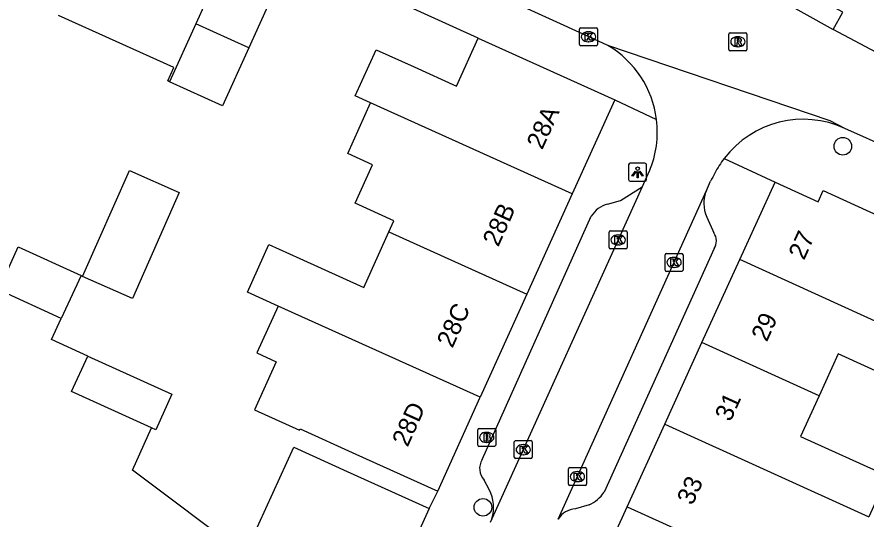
# Model space of a CAD drawing. Extents: x 161845 to 162341, y 381620 to 382158.
# Drawn here: x 162036.15 to 162083.32, y 381718.91 to 381746.81 of the extents above; entities that cross this region are included whole.
import ezdxf

# ---------------------------------------------------------------- set-up
doc = ezdxf.new("R2010")
doc.units = 0
for name, color, linetype in [('IMGEO_Boom', 7, 'Continuous'), ('IMGEO_Brandkraan', 7, 'Continuous'), ('IMGEO_Kolk', 7, 'Continuous'), ('IMGEO_Lichtpunt', 7, 'Continuous'), ('IMGEO_Muur', 7, 'Continuous'), ('IMGEO_Pand', 7, 'Continuous'), ('IMGEO_Pand_nummerreeks', 7, 'Continuous'), ('IMGEO_Rijbaan_lokaal_open', 7, 'Continuous'), ('IMGEO_Rioolput', 7, 'Continuous'), ('IMGEO_Voetpad_open', 7, 'Continuous')]:
    doc.layers.add(name, color=color, linetype=linetype)

msp = doc.modelspace()

# ---------------------------------------------------------------- linework, layer by layer
at = {"layer": 'IMGEO_Boom'}
for centre in [(162082.036, 381739.628), (162062.04, 381719.56)]:
    msp.add_circle(centre, 0.489, dxfattribs=at)
at = {"layer": 'IMGEO_Brandkraan'}
for p, q in [((162061.823, 381723.949), (162062.675, 381723.949)), ((162061.748, 381723.023), (162061.748, 381723.875)), ((162062.236, 381723.729), (162062.261, 381723.729)), ((162062.749, 381723.875), (162062.749, 381723.023)), ((162062.675, 381722.949), (162061.823, 381722.949)), ((162062.259, 381723.169), (162062.234, 381723.169))]:
    msp.add_line(p, q, dxfattribs=at)
for points in [[(162061.823, 381723.949), (162062.675, 381723.949)], [(162061.748, 381723.023), (162061.748, 381723.875)], [(162062.096, 381723.649), (162062.096, 381723.249), (162062.309, 381723.249)], [(162062.327, 381723.649), (162062.096, 381723.649)], [(162062.275, 381723.568), (162062.221, 381723.568), (162062.221, 381723.492)], [(162062.221, 381723.492), (162062.274, 381723.492)], [(162062.283, 381723.416), (162062.221, 381723.416), (162062.221, 381723.335)], [(162062.749, 381723.875), (162062.749, 381723.023)], [(162062.675, 381722.949), (162061.823, 381722.949)], [(162062.221, 381723.335), (162062.283, 381723.335)]]:
    msp.add_lwpolyline(points, dxfattribs=at)
for centre, radius, start, end in [((162061.825, 381723.873), 0.0765, 91.552, 178.448), ((162061.825, 381723.873), 0.0765, 91.552, 178.448), ((162062.673, 381723.873), 0.0765, 1.552, 88.448), ((162062.673, 381723.873), 0.0765, 1.552, 88.448), ((162062.276, 381723.53), 0.0379, 267.8285, 90.9355), ((162062.284, 381723.375), 0.0404, 269.8759, 90.5077), ((162062.331, 381723.504), 0.145, 59.4692, 91.5367), ((162062.356, 381723.551), 0.0922, 285.5137, 58.1501), ((162062.361, 381723.359), 0.105, 301.3115, 78.989), ((162061.825, 381723.025), 0.0765, 181.552, 268.448), ((162061.825, 381723.025), 0.0765, 181.552, 268.448), ((162062.315, 381723.5), 0.251, 268.6676, 293.5347), ((162062.673, 381723.025), 0.0765, 271.552, 358.448), ((162062.673, 381723.025), 0.0765, 271.552, 358.448)]:
    msp.add_arc(centre, radius, start, end, dxfattribs=at)
for centre, major_axis, ratio, start_param, end_param in [((162062.235, 381723.449), (-0.387, 0.002), 0.722429, 4.712389, 7.853982), ((162062.26, 381723.449), (-0.39, 0.002), 0.717154, 1.570796, 4.712389)]:
    msp.add_ellipse(centre, major_axis=major_axis, ratio=ratio, start_param=start_param, end_param=end_param, dxfattribs=at)
at = {"layer": 'IMGEO_Kolk'}
for p, q in [((162067.403, 381745.29), (162067.403, 381746.142)), ((162067.478, 381746.216), (162068.33, 381746.216)), ((162068.404, 381746.142), (162068.404, 381745.29)), ((162067.891, 381745.996), (162067.916, 381745.996)), ((162068.33, 381745.216), (162067.478, 381745.216)), ((162067.914, 381745.436), (162067.889, 381745.436)), ((162069.053, 381733.997), (162069.053, 381734.849)), ((162069.128, 381734.923), (162069.98, 381734.923)), ((162070.054, 381734.849), (162070.054, 381733.997)), ((162069.541, 381734.703), (162069.566, 381734.703)), ((162069.98, 381733.923), (162069.128, 381733.923)), ((162069.564, 381734.143), (162069.539, 381734.143)), ((162072.156, 381732.749), (162072.156, 381733.601)), ((162072.231, 381733.675), (162073.083, 381733.675)), ((162072.644, 381733.455), (162072.669, 381733.455)), ((162073.157, 381733.601), (162073.157, 381732.749)), ((162072.667, 381732.895), (162072.642, 381732.895)), ((162073.083, 381732.675), (162072.231, 381732.675)), ((162063.781, 381722.34), (162063.781, 381723.192)), ((162063.856, 381723.266), (162064.708, 381723.266)), ((162064.269, 381723.046), (162064.294, 381723.046)), ((162064.782, 381723.192), (162064.782, 381722.34)), ((162064.292, 381722.486), (162064.267, 381722.486)), ((162064.708, 381722.266), (162063.856, 381722.266)), ((162066.788, 381720.841), (162066.788, 381721.693)), ((162066.863, 381721.767), (162067.715, 381721.767)), ((162067.276, 381721.547), (162067.301, 381721.547)), ((162067.789, 381721.693), (162067.789, 381720.841)), ((162067.715, 381720.767), (162066.863, 381720.767)), ((162067.299, 381720.987), (162067.274, 381720.987))]:
    msp.add_line(p, q, dxfattribs=at)
for points in [[(162067.403, 381745.29), (162067.403, 381746.142)], [(162067.478, 381746.216), (162068.33, 381746.216)], [(162068.404, 381746.142), (162068.404, 381745.29)], [(162067.724, 381745.916), (162067.847, 381745.916), (162067.847, 381745.765), (162067.977, 381745.916), (162068.141, 381745.916), (162067.995, 381745.765), (162068.148, 381745.516), (162067.996, 381745.516), (162067.911, 381745.68), (162067.847, 381745.613), (162067.847, 381745.516), (162067.724, 381745.516), (162067.724, 381745.916)], [(162068.33, 381745.216), (162067.478, 381745.216)], [(162069.053, 381733.997), (162069.053, 381734.849)], [(162069.128, 381734.923), (162069.98, 381734.923)], [(162070.054, 381734.849), (162070.054, 381733.997)], [(162069.374, 381734.623), (162069.497, 381734.623), (162069.497, 381734.472), (162069.627, 381734.623), (162069.791, 381734.623), (162069.645, 381734.472), (162069.798, 381734.223), (162069.646, 381734.223), (162069.561, 381734.387), (162069.497, 381734.32), (162069.497, 381734.223), (162069.374, 381734.223), (162069.374, 381734.623)], [(162069.98, 381733.923), (162069.128, 381733.923)], [(162072.156, 381732.749), (162072.156, 381733.601)], [(162072.231, 381733.675), (162073.083, 381733.675)], [(162072.477, 381733.375), (162072.6, 381733.375), (162072.6, 381733.224), (162072.73, 381733.375), (162072.894, 381733.375), (162072.748, 381733.224), (162072.901, 381732.975), (162072.749, 381732.975), (162072.664, 381733.139), (162072.6, 381733.072), (162072.6, 381732.975), (162072.477, 381732.975), (162072.477, 381733.375)], [(162073.157, 381733.601), (162073.157, 381732.749)], [(162073.083, 381732.675), (162072.231, 381732.675)], [(162063.781, 381722.34), (162063.781, 381723.192)], [(162063.856, 381723.266), (162064.708, 381723.266)], [(162064.102, 381722.966), (162064.225, 381722.966), (162064.225, 381722.815), (162064.355, 381722.966), (162064.519, 381722.966), (162064.373, 381722.815), (162064.526, 381722.566), (162064.374, 381722.566), (162064.289, 381722.73), (162064.225, 381722.663), (162064.225, 381722.566), (162064.102, 381722.566), (162064.102, 381722.966)], [(162064.782, 381723.192), (162064.782, 381722.34)], [(162064.708, 381722.266), (162063.856, 381722.266)], [(162066.788, 381720.841), (162066.788, 381721.693)], [(162066.863, 381721.767), (162067.715, 381721.767)], [(162067.789, 381721.693), (162067.789, 381720.841)], [(162067.109, 381721.467), (162067.232, 381721.467), (162067.232, 381721.316), (162067.362, 381721.467), (162067.526, 381721.467), (162067.38, 381721.316), (162067.533, 381721.067), (162067.381, 381721.067), (162067.296, 381721.231), (162067.232, 381721.164), (162067.232, 381721.067), (162067.109, 381721.067), (162067.109, 381721.467)], [(162067.715, 381720.767), (162066.863, 381720.767)]]:
    msp.add_lwpolyline(points, dxfattribs=at)
for centre, start, end in [((162067.48, 381746.14), 91.552, 178.448), ((162067.48, 381746.14), 91.552, 178.448), ((162068.328, 381746.14), 1.552, 88.448), ((162068.328, 381746.14), 1.552, 88.448), ((162067.48, 381745.292), 181.552, 268.448), ((162067.48, 381745.292), 181.552, 268.448), ((162068.328, 381745.292), 271.552, 358.448), ((162068.328, 381745.292), 271.552, 358.448), ((162069.13, 381734.847), 91.552, 178.448), ((162069.13, 381734.847), 91.552, 178.448), ((162069.978, 381734.847), 1.552, 88.448), ((162069.978, 381734.847), 1.552, 88.448), ((162069.13, 381733.999), 181.552, 268.448), ((162069.13, 381733.999), 181.552, 268.448), ((162069.978, 381733.999), 271.552, 358.448), ((162069.978, 381733.999), 271.552, 358.448), ((162072.233, 381733.599), 91.552, 178.448), ((162072.233, 381733.599), 91.552, 178.448), ((162073.081, 381733.599), 1.552, 88.448), ((162073.081, 381733.599), 1.552, 88.448), ((162072.233, 381732.751), 181.552, 268.448), ((162072.233, 381732.751), 181.552, 268.448), ((162073.081, 381732.751), 271.552, 358.448), ((162073.081, 381732.751), 271.552, 358.448), ((162063.858, 381723.19), 91.552, 178.448), ((162063.858, 381723.19), 91.552, 178.448), ((162064.706, 381723.19), 1.552, 88.448), ((162064.706, 381723.19), 1.552, 88.448), ((162063.858, 381722.342), 181.552, 268.448), ((162063.858, 381722.342), 181.552, 268.448), ((162064.706, 381722.342), 271.552, 358.448), ((162064.706, 381722.342), 271.552, 358.448), ((162066.865, 381721.691), 91.552, 178.448), ((162066.865, 381721.691), 91.552, 178.448), ((162067.713, 381721.691), 1.552, 88.448), ((162067.713, 381721.691), 1.552, 88.448), ((162066.865, 381720.843), 181.552, 268.448), ((162066.865, 381720.843), 181.552, 268.448), ((162067.713, 381720.843), 271.552, 358.448), ((162067.713, 381720.843), 271.552, 358.448)]:
    msp.add_arc(centre, 0.0765, start, end, dxfattribs=at)
for centre, major_axis, ratio, start_param, end_param in [((162067.89, 381745.716), (-0.387, 0.002), 0.722429, 4.712389, 7.853982), ((162067.915, 381745.716), (-0.39, 0.002), 0.717154, 1.570796, 4.712389), ((162069.54, 381734.423), (-0.387, 0.002), 0.722429, 4.712389, 7.853982), ((162069.565, 381734.423), (-0.39, 0.002), 0.717154, 1.570796, 4.712389), ((162072.643, 381733.175), (-0.387, 0.002), 0.722429, 4.712389, 7.853982), ((162072.668, 381733.175), (-0.39, 0.002), 0.717154, 1.570796, 4.712389), ((162064.268, 381722.766), (-0.387, 0.002), 0.722429, 4.712389, 7.853982), ((162064.293, 381722.766), (-0.39, 0.002), 0.717154, 1.570796, 4.712389), ((162067.275, 381721.267), (-0.387, 0.002), 0.722429, 4.712389, 7.853982), ((162067.3, 381721.267), (-0.39, 0.002), 0.717154, 1.570796, 4.712389)]:
    msp.add_ellipse(centre, major_axis=major_axis, ratio=ratio, start_param=start_param, end_param=end_param, dxfattribs=at)
at = {"layer": 'IMGEO_Lichtpunt'}
for p, q in [((162070.134, 381738.588), (162070.134, 381737.781)), ((162070.134, 381738.588), (162070.134, 381737.781)), ((162071.036, 381738.683), (162070.228, 381738.683)), ((162071.036, 381738.683), (162070.228, 381738.683)), ((162071.13, 381737.781), (162071.13, 381738.588)), ((162071.13, 381737.781), (162071.13, 381738.588)), ((162070.228, 381737.687), (162071.036, 381737.687)), ((162070.228, 381737.687), (162071.036, 381737.687))]:
    msp.add_line(p, q, dxfattribs=at)
for points in [[(162070.508, 381738.252), (162070.547, 381738.224), (162070.359, 381737.962), (162070.321, 381737.989), (162070.508, 381738.252)], [(162070.61, 381738.204), (162070.657, 381738.204), (162070.657, 381737.882), (162070.61, 381737.882), (162070.61, 381738.204)], [(162070.72, 381738.224), (162070.758, 381738.251), (162070.945, 381737.989), (162070.906, 381737.961), (162070.72, 381738.224)]]:
    msp.add_lwpolyline(points, dxfattribs=at)
msp.add_circle((162070.633, 381738.386), 0.0994, dxfattribs=at)
for centre, start, end in [((162070.228, 381738.588), 90, 180), ((162070.228, 381738.588), 90, 180), ((162071.036, 381738.588), 0, 90), ((162071.036, 381738.588), 0, 90), ((162070.228, 381737.781), 180, 270), ((162070.228, 381737.781), 180, 270), ((162071.036, 381737.781), 270, 0), ((162071.036, 381737.781), 270, 360)]:
    msp.add_arc(centre, 0.0946, start, end, dxfattribs=at)
at = {"layer": 'IMGEO_Muur'}
msp.add_lwpolyline([(162061.772, 381745.637), (162051.408, 381750.366)], dxfattribs=at)
at = {"layer": 'IMGEO_Pand'}
for points in [[(162048.46, 381751.697), (162047.692, 381750), (162046.08, 381746.435)], [(162051.408, 381750.366), (162049.031, 381745.101)], [(162044.624, 381743.216), (162044.525, 381743.261), (162044.858, 381744), (162038.465, 381746.887)], [(162046.08, 381746.435), (162044.624, 381743.216)], [(162049.031, 381745.101), (162046.08, 381746.435)], [(162055.802, 381742.043), (162054.948, 381742.429), (162056.105, 381744.987), (162058.214, 381744.033), (162060.564, 381742.969), (162061.772, 381745.637)], [(162061.772, 381745.637), (162069.369, 381742.199)], [(162049.031, 381745.101), (162047.578, 381741.883), (162044.624, 381743.216)], [(162056.82, 381734.869), (162057.097, 381735.481), (162054.936, 381736.459), (162055.904, 381738.6), (162054.526, 381739.223), (162055.802, 381742.043)], [(162067.005, 381736.977), (162055.802, 381742.043)], [(162069.369, 381742.199), (162067.005, 381736.977)], [(162042.399, 381738.276), (162045.166, 381737.054), (162042.567, 381731.172), (162039.801, 381732.394), (162042.399, 381738.276)], [(162076.306, 381733.328), (162078.267, 381737.638)], [(162078.267, 381737.638), (162080.663, 381736.548), (162080.942, 381737.161), (162085.927, 381734.893)], [(162067.005, 381736.977), (162064.483, 381731.405)], [(162050.667, 381730.749), (162048.953, 381731.524), (162050.145, 381734.159), (162051.86, 381733.383), (162055.419, 381731.773), (162056.82, 381734.869)], [(162056.82, 381734.869), (162064.483, 381731.405)], [(162035.117, 381731.657), (162036.215, 381734.047), (162039.711, 381732.441), (162038.613, 381730.051)], [(162074.208, 381728.716), (162076.306, 381733.328)], [(162087.601, 381728.189), (162076.306, 381733.328)], [(162038.613, 381730.051), (162035.117, 381731.657)], [(162064.483, 381731.405), (162061.89, 381725.676)], [(162050.667, 381730.749), (162049.486, 381728.139), (162050.56, 381727.653), (162049.347, 381724.972), (162051.844, 381723.842), (162051.879, 381723.919), (162054.973, 381722.519), (162059.528, 381720.458)], [(162061.89, 381725.676), (162050.667, 381730.749)], [(162072.147, 381724.183), (162074.208, 381728.716)], [(162080.711, 381725.757), (162074.208, 381728.716)], [(162087.601, 381728.189), (162086.563, 381725.907), (162081.771, 381728.087), (162080.711, 381725.757)], [(162043.634, 381723.976), (162039.186, 381725.994), (162040.082, 381727.969)], [(162040.082, 381727.969), (162044.759, 381725.847), (162043.863, 381723.872), (162043.634, 381723.976)], [(162059.528, 381720.458), (162061.89, 381725.676)], [(162080.711, 381725.757), (162079.684, 381723.498), (162084.511, 381721.303), (162083.477, 381719.029)], [(162070.06, 381719.595), (162072.147, 381724.183)], [(162072.147, 381724.183), (162083.477, 381719.029)], [(162048.815, 381716.934), (162051.526, 381722.912), (162054.491, 381721.55), (162059.046, 381719.488)], [(162059.046, 381719.488), (162056.347, 381713.524)], [(162067.969, 381714.998), (162070.06, 381719.595)], [(162070.06, 381719.595), (162076.547, 381716.643)]]:
    msp.add_lwpolyline(points, dxfattribs=at)
at = {"layer": 'IMGEO_Rijbaan_lokaal_open'}
for points in [[(162068.985, 381745.23), (162068.214, 381745.584), (162056.86, 381750.762), (162052.77, 381752.631)], [(162073.51, 381750.574), (162081.506, 381746.115)], [(162084.495, 381744.526), (162081.506, 381746.115)], [(162082.15, 381740.62), (162081.324, 381741.038), (162068.985, 381745.23)], [(162087.294, 381738.315), (162082.15, 381740.62)], [(162071.284, 381738.243), (162070.89, 381737.372)], [(162074.46, 381737.176), (162074.689, 381737.685)], [(162070.89, 381737.372), (162062.541, 381718.913)], [(162066.227, 381718.911), (162074.46, 381737.176)], [(162040.082, 381727.969), (162038.075, 381728.88), (162038.613, 381730.051)], [(162048.815, 381716.934), (162042.565, 381721.62), (162043.634, 381723.976)], [(162062.541, 381718.913), (162062.449, 381718.709)]]:
    msp.add_lwpolyline(points, dxfattribs=at)
for centre, radius, start, end in [((162066.141, 381740.423), 5.586, 7.1726, 59.393), ((162066.148, 381740.421), 5.579, 337.0159, 7.1926), ((162079.84, 381735.589), 5.536, 65.3364, 142.6075), ((162079.878, 381735.562), 5.582, 142.6195, 152.4839), ((162079.843, 381735.285), 5.685, 149.8456, 155.0316)]:
    msp.add_arc(centre, radius, start, end, dxfattribs=at)
at = {"layer": 'IMGEO_Rioolput'}
for p, q in [((162075.705, 381745.009), (162075.705, 381745.861)), ((162075.78, 381745.935), (162076.632, 381745.935)), ((162076.193, 381745.715), (162076.218, 381745.715)), ((162076.706, 381745.861), (162076.706, 381745.009)), ((162076.216, 381745.155), (162076.191, 381745.155)), ((162076.632, 381744.935), (162075.78, 381744.935))]:
    msp.add_line(p, q, dxfattribs=at)
for points in [[(162075.705, 381745.009), (162075.705, 381745.861)], [(162075.78, 381745.935), (162076.632, 381745.935)], [(162076.294, 381745.633), (162076.042, 381745.635), (162076.042, 381745.235)], [(162076.706, 381745.861), (162076.706, 381745.009)], [(162076.042, 381745.235), (162076.166, 381745.235), (162076.166, 381745.397), (162076.177, 381745.397)], [(162076.22, 381745.554), (162076.166, 381745.554), (162076.166, 381745.473)], [(162076.166, 381745.473), (162076.218, 381745.473)], [(162076.224, 381745.368), (162076.295, 381745.235), (162076.435, 381745.235), (162076.37, 381745.361)], [(162076.632, 381744.935), (162075.78, 381744.935)]]:
    msp.add_lwpolyline(points, dxfattribs=at)
for centre, radius, start, end in [((162075.782, 381745.859), 0.0765, 91.552, 178.448), ((162075.782, 381745.859), 0.0765, 91.552, 178.448), ((162076.293, 381745.523), 0.109, 350.3612, 89.416), ((162076.63, 381745.859), 0.0765, 1.552, 88.448), ((162076.63, 381745.859), 0.0765, 1.552, 88.448), ((162076.176, 381745.344), 0.0533, 26.0293, 88.6989), ((162076.202, 381745.662), 0.19, 274.7715, 282.9687), ((162076.226, 381745.458), 0.0964, 77.0061, 93.1865), ((162076.24, 381745.515), 0.0378, 276.6634, 79.6772), ((162076.291, 381745.523), 0.112, 277.5842, 350.9817), ((162076.275, 381745.308), 0.108, 29.5134, 73.7905), ((162075.782, 381745.011), 0.0765, 181.552, 268.448), ((162075.782, 381745.011), 0.0765, 181.552, 268.448), ((162076.63, 381745.011), 0.0765, 271.552, 358.448), ((162076.63, 381745.011), 0.0765, 271.552, 358.448)]:
    msp.add_arc(centre, radius, start, end, dxfattribs=at)
for centre, major_axis, ratio, start_param, end_param in [((162076.192, 381745.435), (-0.387, 0.002), 0.722429, 4.712389, 7.853982), ((162076.217, 381745.435), (-0.39, 0.002), 0.717154, 1.570796, 4.712389)]:
    msp.add_ellipse(centre, major_axis=major_axis, ratio=ratio, start_param=start_param, end_param=end_param, dxfattribs=at)
at = {"layer": 'IMGEO_Voetpad_open'}
for points in [[(162061.772, 381745.637), (162051.408, 381750.366)], [(162081.506, 381746.115), (162082.026, 381747.073), (162079.471, 381748.488)], [(162069.369, 381742.199), (162071.683, 381741.12)], [(162075.442, 381738.951), (162078.267, 381737.638)], [(162068.968, 381736.414), (162069.691, 381736.607), (162070.89, 381737.372)], [(162061.996, 381722.217), (162068.057, 381735.737)], [(162074.48, 381735.689), (162074.865, 381734.814)], [(162074.881, 381733.938), (162068.77, 381720.405)], [(162062.384, 381720.543), (162062.115, 381721.075)], [(162059.046, 381719.488), (162059.528, 381720.458)], [(162067.935, 381719.703), (162067.174, 381719.484)]]:
    msp.add_lwpolyline(points, dxfattribs=at)
for centre, radius, start, end in [((162076.14, 381736.455), 1.828, 156.7751, 204.766), ((162069.383, 381734.905), 1.565, 105.3599, 147.8751), ((162074.236, 381734.364), 0.773, 326.5491, 35.5437), ((162062.792, 381721.723), 0.937, 148.1553, 223.7426), ((162060.5, 381719.539), 2.134, 342.9449, 28.0585), ((162067.179, 381721.45), 1.903, 293.4007, 326.7081), ((162067.275, 381718.248), 1.24, 94.672, 147.6816)]:
    msp.add_arc(centre, radius, start, end, dxfattribs=at)

# ---------------------------------------------------------------- texts
at = {"layer": 'IMGEO_Pand_nummerreeks'}
for s, rotation, p in [('28A', 65.6463, (162065.332, 381739.392)), ('28B', 65.6438, (162062.889, 381733.995)), ('27', 65.5401, (162079.878, 381733.256)), ('28C', 65.6463, (162060.343, 381728.367)), ('29', 65.5401, (162077.812, 381728.714)), ('31', 65.5401, (162075.791, 381724.275)), ('28D', 65.6438, (162057.854, 381722.871)), ('33', 65.5401, (162073.679, 381719.63))]:
    msp.add_text(s, height=1, rotation=rotation, dxfattribs=at).set_placement(p)

doc.saveas('drawing.dxf')
